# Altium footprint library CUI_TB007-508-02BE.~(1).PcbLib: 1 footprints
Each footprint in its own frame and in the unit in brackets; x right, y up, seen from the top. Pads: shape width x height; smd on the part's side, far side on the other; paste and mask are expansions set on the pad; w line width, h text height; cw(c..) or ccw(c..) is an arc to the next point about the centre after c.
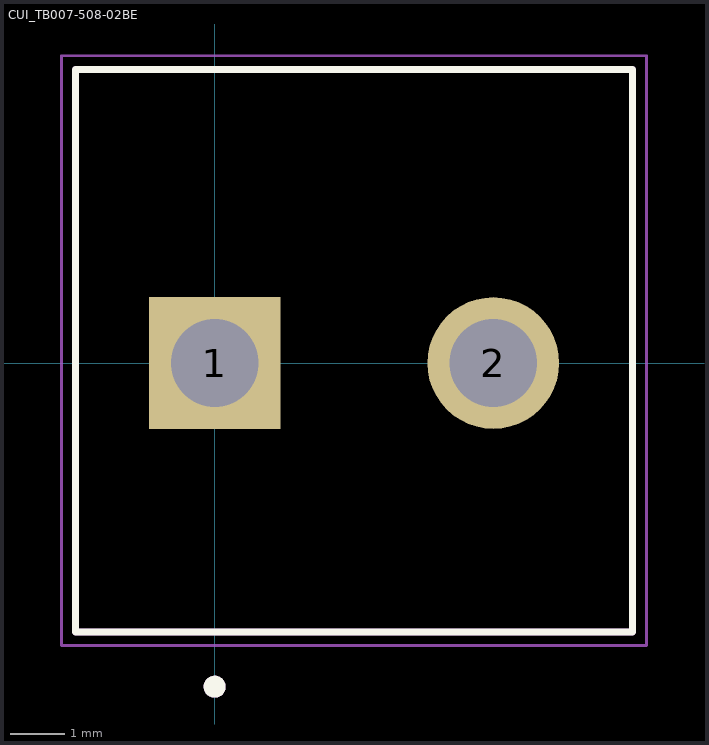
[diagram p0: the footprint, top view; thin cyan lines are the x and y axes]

## CUI_TB007-508-02BE [mm]
pads (2):
  rect 2.4x2.4 / inner round 2.4 / far side rect 2.4x2.4 hole 1.6: 1(0,0)
  round 2.4 hole 1.6: 2(5.08,0)
Top Overlay:
  circle w0.2: c0,-5.9 r0.1
  lines w0.127: -2.54,-4.9 -2.54,5.35 7.62,5.35 7.62,-4.9 -2.54,-4.9
Assembly Top:
  circle w0.2: c0,-5.9 r0.1
  lines w0.127: -2.54,-4.9 -2.54,5.35 7.62,5.35 7.62,-4.9 -2.54,-4.9
Courtyard Top:
  lines w0.05: -2.79,-5.15 7.87,-5.15 7.87,5.6 -2.79,5.6 -2.79,-5.15
3D body "step_temp.STEP": height 14, standoff -3.7, extent 0,-7.62 10.25,3.14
